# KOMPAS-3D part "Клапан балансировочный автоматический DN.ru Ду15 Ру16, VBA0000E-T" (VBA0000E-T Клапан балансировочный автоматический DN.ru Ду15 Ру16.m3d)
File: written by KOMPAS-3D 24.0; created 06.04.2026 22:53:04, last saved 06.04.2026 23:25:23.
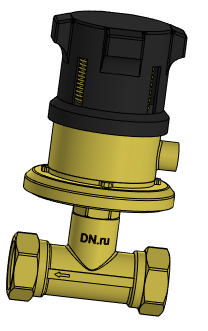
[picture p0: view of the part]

Document properties: Автор: tyuri; Полное имя файла: D:\Аутсорс\Клапан балансировочный автоматический DN.ru VBA0000E-T Ду15 Ру16\DN15\VBA0000E-T Клапан балансировочный автоматический DN.ru Ду15 Ру16.m3d

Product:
- Body: Тело 6  | qty 1
    Масса: 1.051613
- Part/product: Клапан балансировочный автоматический DN.ru Ду15 Ру16  | designation VBA0000E-T
    Масса: 0.675
    Раздел спецификации: Прочие изделия
    Примечание: D080-01200

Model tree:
1. Операция без истории:1

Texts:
  VBA0000E-T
